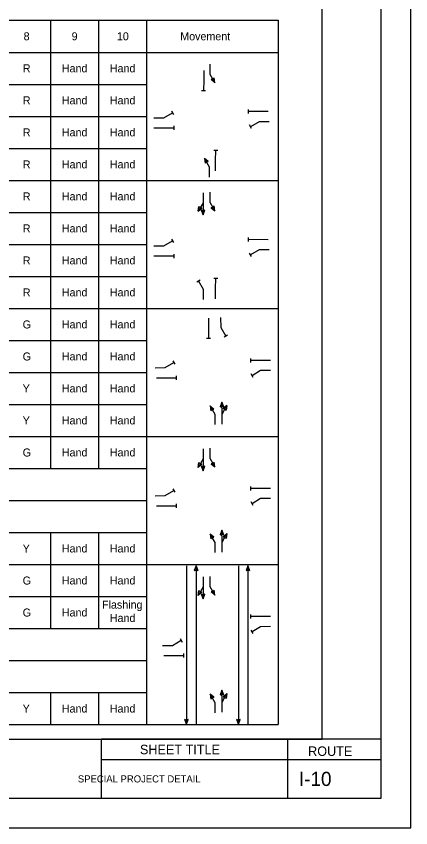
# Model space of a CAD drawing. Extents: x 515543 to 517243, y 660510 to 662861.
# Drawn here: x 516909 to 517243, y 660510 to 661197 of the extents above; entities that cross this region are included whole.
import ezdxf

# ---------------------------------------------------------------- set-up
doc = ezdxf.new("R2010")
doc.units = 0
for name, color, linetype in [('ANNO-SHT', 7, 'Continuous'), ('ANNO-TXT', 7, 'Continuous'), ('Default', 7, 'Continuous'), ('Level 6', 7, 'Continuous'), ('Level 62', 7, 'Continuous'), ('SHT-BDR', 7, 'Continuous'), ('SHT-BNDRY', 7, 'Continuous')]:
    doc.layers.add(name, color=color, linetype=linetype)

msp = doc.modelspace()

# ---------------------------------------------------------------- linework, layer by layer
at = {"layer": 'ANNO-TXT'}
for p, q in [((516980.81, 660567.94), (517138.45, 660567.94)), ((517138.45, 660567.94), (517217.52, 660567.94))]:
    msp.add_line(p, q, dxfattribs=at)
at = {"layer": 'Default'}
for p, q in [((516439.72, 661193.38), (517130.34, 661193.38)), ((516937.41, 661193.38), (516937.41, 660814.21)), ((516978.03, 661193.38), (516978.03, 660814.21)), ((517018.66, 661193.38), (517018.66, 660597.54)), ((517130.34, 661193.38), (517130.34, 660597.54)), ((516439.72, 661166.29), (517130.34, 661166.29)), ((517072.48, 661156.28), (517072.48, 661147.81)), ((517067.35, 661150.92), (517067.19, 661142.35)), ((517072.48, 661147.81), (517076.71, 661140.48)), ((516520.97, 661139.21), (517018.66, 661139.21)), ((517067.19, 661142.35), (517067.13, 661133.89)), ((517073.47, 661143.2), (517074.93, 661143.56)), ((517076.71, 661140.48), (517073.47, 661143.2)), ((517074.93, 661143.56), (517075.97, 661144.65)), ((517076.71, 661140.48), (517075.97, 661144.65)), ((517065.43, 661133.9), (517068.82, 661133.87)), ((517104.78, 661117.95), (517104.75, 661114.57)), ((516520.97, 661112.13), (517018.66, 661112.13)), ((516693.66, 661112.13), (517018.66, 661112.13)), ((517025.09, 661110.97), (517033.56, 661110.97)), ((517033.56, 661110.97), (517040.89, 661115.2)), ((517040.04, 661116.67), (517041.73, 661113.73)), ((517121.8, 661116.12), (517104.76, 661116.26)), ((517042.17, 661100.63), (517042.2, 661104.01)), ((517107.78, 661101.91), (517106.08, 661104.84)), ((517114.26, 661107.61), (517106.93, 661103.38)), ((517122.72, 661107.61), (517114.26, 661107.61)), ((517025.14, 661102.46), (517042.18, 661102.32)), ((516520.97, 661085.04), (517018.66, 661085.04)), ((517072.02, 661069.27), (517067.78, 661076.6)), ((517067.78, 661076.6), (517071.03, 661073.88)), ((517067.78, 661076.6), (517068.52, 661072.43)), ((517079.06, 661083.18), (517075.68, 661083.21)), ((517077.3, 661074.73), (517077.37, 661083.19)), ((517069.56, 661073.52), (517068.52, 661072.43)), ((517071.03, 661073.88), (517069.56, 661073.52)), ((517077.14, 661066.16), (517077.3, 661074.73)), ((517072.02, 661060.8), (517072.02, 661069.27)), ((516439.72, 661057.96), (517130.34, 661057.96)), ((516937.41, 661057.96), (516978.03, 661057.96)), ((516978.03, 661057.96), (517018.66, 661057.96)), ((517066.65, 661047.57), (517066.65, 661039.11)), ((517066.65, 661047.57), (517066.65, 661039.11)), ((517072.48, 661047.94), (517072.48, 661039.48)), ((517066.65, 661039.11), (517062.41, 661031.78)), ((517062.41, 661031.78), (517063.15, 661035.95)), ((517064.19, 661034.86), (517063.15, 661035.95)), ((517066.65, 661039.11), (517066.75, 661028.9)), ((517072.48, 661039.48), (517076.71, 661032.15)), ((517073.47, 661034.87), (517074.93, 661035.23)), ((517074.93, 661035.23), (517075.97, 661036.32)), ((517076.71, 661032.15), (517075.97, 661036.32)), ((516520.97, 661030.88), (517018.66, 661030.88)), ((517062.41, 661031.78), (517065.66, 661034.5)), ((517065.66, 661034.5), (517064.19, 661034.86)), ((517066.75, 661028.9), (517065.25, 661032.86)), ((517065.25, 661032.86), (517066.71, 661032.45)), ((517066.71, 661032.45), (517068.15, 661032.89)), ((517066.75, 661028.9), (517068.15, 661032.89)), ((517076.71, 661032.15), (517073.47, 661034.87)), ((517040.04, 661008.33), (517041.73, 661005.4)), ((517104.78, 661009.62), (517104.75, 661006.23)), ((517121.8, 661007.79), (517104.76, 661007.92)), ((516520.97, 661003.79), (517018.66, 661003.79)), ((516693.66, 661003.79), (517018.66, 661003.79)), ((517025.09, 661002.63), (517033.56, 661002.63)), ((517033.56, 661002.63), (517040.89, 661006.87)), ((517025.14, 660994.12), (517042.18, 660993.99)), ((517042.17, 660992.29), (517042.2, 660995.68)), ((517107.78, 660993.58), (517106.08, 660996.51)), ((517114.26, 660999.28), (517106.93, 660995.04)), ((517122.72, 660999.28), (517114.26, 660999.28)), ((516520.97, 660976.71), (517018.66, 660976.71)), ((517061.3, 660972.26), (517064.24, 660973.95)), ((517079.06, 660974.85), (517075.68, 660974.88)), ((517077.3, 660966.4), (517077.37, 660974.86)), ((517067, 660965.77), (517062.77, 660973.1)), ((517067, 660957.31), (517067, 660965.77)), ((517077.14, 660957.82), (517077.3, 660966.4)), ((516439.72, 660949.63), (517130.34, 660949.63)), ((517071.38, 660941.4), (517071.31, 660932.83)), ((517081.51, 660942.02), (517081.6, 660933.56)), ((517071.31, 660932.83), (517071.33, 660924.36)), ((517081.6, 660933.56), (517085.91, 660926.28)), ((517087.37, 660927.14), (517084.45, 660925.41)), ((516520.97, 660922.54), (517008.47, 660922.54)), ((516520.97, 660922.54), (517018.66, 660922.54)), ((517069.64, 660924.36), (517073.02, 660924.37)), ((517041.12, 660905.33), (517042.84, 660902.41)), ((517106.71, 660907.3), (517106.72, 660903.92)), ((517123.75, 660905.65), (517106.71, 660905.61)), ((517026.23, 660899.47), (517034.69, 660899.56)), ((517034.69, 660899.56), (517041.98, 660903.87)), ((516520.97, 660895.46), (517018.66, 660895.46)), ((516520.97, 660895.46), (517018.66, 660895.46)), ((516693.66, 660895.46), (517018.66, 660895.46)), ((516693.66, 660895.46), (517018.66, 660895.46)), ((517027.24, 660890.97), (517044.28, 660891.01)), ((517044.29, 660889.32), (517044.28, 660892.71)), ((517109, 660891.29), (517107.28, 660894.2)), ((517115.43, 660897.05), (517108.14, 660892.74)), ((517123.89, 660897.14), (517115.43, 660897.05)), ((517082.51, 660870.44), (517081.16, 660866.43)), ((517082.72, 660860.23), (517082.51, 660870.44)), ((517082.51, 660870.44), (517084.05, 660866.5)), ((516520.97, 660868.38), (517008.47, 660868.38)), ((516520.97, 660868.38), (517018.66, 660868.38)), ((517076.9, 660859.8), (517072.59, 660867.09)), ((517072.59, 660867.09), (517075.86, 660864.4)), ((517072.59, 660867.09), (517073.37, 660862.93)), ((517074.4, 660864.03), (517073.37, 660862.93)), ((517075.86, 660864.4), (517074.4, 660864.03)), ((517082.59, 660866.89), (517081.16, 660866.43)), ((517084.05, 660866.5), (517082.59, 660866.89)), ((517082.72, 660860.23), (517086.88, 660867.61)), ((517086.88, 660867.61), (517083.67, 660864.85)), ((517083.67, 660864.85), (517085.14, 660864.51)), ((517085.14, 660864.51), (517086.19, 660863.43)), ((517086.88, 660867.61), (517086.19, 660863.43)), ((517076.99, 660851.34), (517076.9, 660859.8)), ((517082.81, 660851.77), (517082.72, 660860.23)), ((517082.81, 660851.77), (517082.72, 660860.23)), ((516439.72, 660841.29), (517130.34, 660841.29)), ((517066.65, 660830.9), (517066.65, 660822.44)), ((517066.65, 660830.9), (517066.65, 660822.44)), ((517072.48, 660831.28), (517072.48, 660822.81)), ((517066.65, 660822.44), (517062.41, 660815.11)), ((517066.65, 660822.44), (517066.75, 660812.23)), ((517072.48, 660822.81), (517076.71, 660815.48)), ((517062.41, 660815.11), (517063.15, 660819.28)), ((517062.41, 660815.11), (517065.66, 660817.83)), ((517064.19, 660818.19), (517063.15, 660819.28)), ((517065.66, 660817.83), (517064.19, 660818.19)), ((517066.75, 660812.23), (517065.25, 660816.19)), ((517065.25, 660816.19), (517066.71, 660815.79)), ((517066.71, 660815.79), (517068.15, 660816.23)), ((517066.75, 660812.23), (517068.15, 660816.23)), ((517073.47, 660818.2), (517074.93, 660818.56)), ((517076.71, 660815.48), (517073.47, 660818.2)), ((517074.93, 660818.56), (517075.97, 660819.65)), ((517076.71, 660815.48), (517075.97, 660819.65)), ((516520.97, 660814.21), (517008.47, 660814.21)), ((516520.97, 660814.21), (517018.66, 660814.21)), ((517034.69, 660791.23), (517041.98, 660795.54)), ((517041.12, 660797), (517042.84, 660794.08)), ((517106.71, 660798.97), (517106.72, 660795.58)), ((517123.75, 660797.32), (517106.71, 660797.28)), ((517026.23, 660791.14), (517034.69, 660791.23)), ((517115.43, 660788.72), (517108.14, 660784.41)), ((517123.89, 660788.81), (517115.43, 660788.72)), ((516520.97, 660787.13), (517018.66, 660787.13)), ((516520.97, 660787.13), (517018.66, 660787.13)), ((516693.66, 660787.13), (517018.66, 660787.13)), ((516693.66, 660787.13), (517018.66, 660787.13)), ((517027.24, 660782.64), (517044.28, 660782.68)), ((517044.29, 660780.99), (517044.28, 660784.37)), ((517109, 660782.95), (517107.28, 660785.87)), ((517082.51, 660762.1), (517081.16, 660758.1)), ((517082.72, 660751.9), (517082.51, 660762.1)), ((517082.51, 660762.1), (517084.05, 660758.16)), ((516520.97, 660760.04), (517008.47, 660760.04)), ((516520.97, 660760.04), (517018.66, 660760.04)), ((516937.41, 660760.04), (516937.41, 660678.79)), ((516978.03, 660760.04), (516978.03, 660678.79)), ((517076.9, 660751.47), (517072.59, 660758.75)), ((517072.59, 660758.75), (517075.86, 660756.07)), ((517072.59, 660758.75), (517073.37, 660754.59)), ((517074.4, 660755.69), (517073.37, 660754.59)), ((517075.86, 660756.07), (517074.4, 660755.69)), ((517082.59, 660758.55), (517081.16, 660758.1)), ((517084.05, 660758.16), (517082.59, 660758.55)), ((517082.72, 660751.9), (517086.88, 660759.27)), ((517086.88, 660759.27), (517083.67, 660756.52)), ((517083.67, 660756.52), (517085.14, 660756.18)), ((517085.14, 660756.18), (517086.19, 660755.1)), ((517086.88, 660759.27), (517086.19, 660755.1)), ((517076.99, 660743), (517076.9, 660751.47)), ((517082.81, 660743.44), (517082.72, 660751.9)), ((517082.81, 660743.44), (517082.72, 660751.9)), ((516439.72, 660732.96), (517130.34, 660732.96)), ((517052.71, 660731.84), (517052.71, 660597.79)), ((517060.7, 660731.84), (517059.25, 660727.86)), ((517060.7, 660728.28), (517059.25, 660727.86)), ((517060.7, 660731.84), (517060.7, 660597.79)), ((517060.7, 660731.84), (517062.14, 660727.86)), ((517062.14, 660727.86), (517060.7, 660728.28)), ((517096.65, 660731.84), (517096.65, 660597.79)), ((517104.64, 660731.84), (517103.19, 660727.86)), ((517104.64, 660728.28), (517103.19, 660727.86)), ((517104.64, 660731.84), (517104.64, 660597.79)), ((517104.64, 660731.84), (517106.09, 660727.86)), ((517106.09, 660727.86), (517104.64, 660728.28)), ((517066.65, 660722.57), (517066.65, 660714.11)), ((517066.65, 660722.57), (517066.65, 660714.11)), ((517072.48, 660722.94), (517072.48, 660714.48)), ((517066.65, 660714.11), (517062.41, 660706.78)), ((517066.65, 660714.11), (517066.75, 660703.9)), ((517072.48, 660714.48), (517076.71, 660707.15)), ((516520.97, 660705.88), (517008.47, 660705.88)), ((516520.97, 660705.88), (517018.66, 660705.88)), ((517062.41, 660706.78), (517063.15, 660710.95)), ((517062.41, 660706.78), (517065.66, 660709.5)), ((517064.19, 660709.86), (517063.15, 660710.95)), ((517065.66, 660709.5), (517064.19, 660709.86)), ((517066.75, 660703.9), (517065.25, 660707.86)), ((517065.25, 660707.86), (517066.71, 660707.45)), ((517066.71, 660707.45), (517068.15, 660707.89)), ((517066.75, 660703.9), (517068.15, 660707.89)), ((517073.47, 660709.87), (517074.93, 660710.23)), ((517076.71, 660707.15), (517073.47, 660709.87)), ((517074.93, 660710.23), (517075.97, 660711.32)), ((517076.71, 660707.15), (517075.97, 660711.32)), ((517106.71, 660690.63), (517106.72, 660687.25)), ((517123.75, 660688.98), (517106.71, 660688.94)), ((516520.97, 660678.79), (517018.66, 660678.79)), ((516520.97, 660678.79), (517018.66, 660678.79)), ((516693.66, 660678.79), (517018.66, 660678.79)), ((516693.66, 660678.79), (517018.66, 660678.79)), ((517115.43, 660680.38), (517108.14, 660676.08)), ((517123.89, 660680.47), (517115.43, 660680.38)), ((517109, 660674.62), (517107.28, 660677.53)), ((517032.45, 660664.46), (517040.91, 660664.54)), ((517040.91, 660664.54), (517048.2, 660668.85)), ((517047.33, 660670.31), (517049.06, 660667.4)), ((517050.5, 660654.3), (517050.5, 660657.69)), ((516520.97, 660651.71), (517008.47, 660651.71)), ((516520.97, 660651.71), (517018.66, 660651.71)), ((517033.46, 660655.95), (517050.5, 660656)), ((516520.97, 660624.63), (517018.66, 660624.63)), ((516520.97, 660624.63), (517008.47, 660624.63)), ((516520.97, 660624.63), (517008.47, 660624.63)), ((516937.41, 660624.63), (516937.41, 660597.54)), ((516978.03, 660624.63), (516978.03, 660597.54)), ((517076.9, 660616.05), (517072.59, 660623.34)), ((517072.59, 660623.34), (517075.86, 660620.65)), ((517072.59, 660623.34), (517073.37, 660619.18)), ((517082.51, 660626.69), (517081.16, 660622.68)), ((517082.72, 660616.48), (517082.51, 660626.69)), ((517082.51, 660626.69), (517084.05, 660622.75)), ((517082.72, 660616.48), (517086.88, 660623.86)), ((517086.88, 660623.86), (517083.67, 660621.1)), ((517086.88, 660623.86), (517086.19, 660619.68)), ((517074.4, 660620.28), (517073.37, 660619.18)), ((517075.86, 660620.65), (517074.4, 660620.28)), ((517082.59, 660623.14), (517081.16, 660622.68)), ((517084.05, 660622.75), (517082.59, 660623.14)), ((517082.81, 660608.02), (517082.72, 660616.48)), ((517082.81, 660608.02), (517082.72, 660616.48)), ((517083.67, 660621.1), (517085.14, 660620.76)), ((517085.14, 660620.76), (517086.19, 660619.68)), ((517076.99, 660607.59), (517076.9, 660616.05)), ((516439.72, 660597.54), (517130.34, 660597.54)), ((517052.71, 660597.79), (517051.26, 660601.76)), ((517051.26, 660601.76), (517052.71, 660601.34)), ((517052.71, 660597.79), (517054.15, 660601.76)), ((517052.71, 660601.34), (517054.15, 660601.76)), ((517096.65, 660597.79), (517095.2, 660601.76)), ((517095.2, 660601.76), (517096.65, 660601.34)), ((517096.65, 660597.79), (517098.1, 660601.76)), ((517096.65, 660601.34), (517098.1, 660601.76))]:
    msp.add_line(p, q, dxfattribs=at)
for points in [[(517073.47, 661143.2), (517076.71, 661140.48), (517075.97, 661144.65), (517074.93, 661143.56), (517073.47, 661143.2)], [(517071.03, 661073.88), (517067.78, 661076.6), (517068.52, 661072.43), (517069.56, 661073.52), (517071.03, 661073.88)], [(517065.66, 661034.5), (517062.41, 661031.78), (517063.15, 661035.95), (517064.19, 661034.86), (517065.66, 661034.5)], [(517073.47, 661034.87), (517076.71, 661032.15), (517075.97, 661036.32), (517074.93, 661035.23), (517073.47, 661034.87)], [(517065.25, 661032.86), (517066.75, 661028.9), (517068.15, 661032.89), (517066.71, 661032.45), (517065.25, 661032.86)], [(517084.05, 660866.5), (517082.51, 660870.44), (517081.16, 660866.43), (517082.59, 660866.89), (517084.05, 660866.5)], [(517075.86, 660864.4), (517072.59, 660867.09), (517073.37, 660862.93), (517074.4, 660864.03), (517075.86, 660864.4)], [(517083.67, 660864.85), (517086.88, 660867.61), (517086.19, 660863.43), (517085.14, 660864.51), (517083.67, 660864.85)], [(517065.66, 660817.83), (517062.41, 660815.11), (517063.15, 660819.28), (517064.19, 660818.19), (517065.66, 660817.83)], [(517065.25, 660816.19), (517066.75, 660812.23), (517068.15, 660816.23), (517066.71, 660815.79), (517065.25, 660816.19)], [(517073.47, 660818.2), (517076.71, 660815.48), (517075.97, 660819.65), (517074.93, 660818.56), (517073.47, 660818.2)], [(517084.05, 660758.16), (517082.51, 660762.1), (517081.16, 660758.1), (517082.59, 660758.55), (517084.05, 660758.16)], [(517075.86, 660756.07), (517072.59, 660758.75), (517073.37, 660754.59), (517074.4, 660755.69), (517075.86, 660756.07)], [(517083.67, 660756.52), (517086.88, 660759.27), (517086.19, 660755.1), (517085.14, 660756.18), (517083.67, 660756.52)], [(517062.14, 660727.86), (517060.7, 660731.84), (517059.25, 660727.86), (517060.7, 660728.28), (517062.14, 660727.86)], [(517106.09, 660727.86), (517104.64, 660731.84), (517103.19, 660727.86), (517104.64, 660728.28), (517106.09, 660727.86)], [(517065.66, 660709.5), (517062.41, 660706.78), (517063.15, 660710.95), (517064.19, 660709.86), (517065.66, 660709.5)], [(517065.25, 660707.86), (517066.75, 660703.9), (517068.15, 660707.89), (517066.71, 660707.45), (517065.25, 660707.86)], [(517073.47, 660709.87), (517076.71, 660707.15), (517075.97, 660711.32), (517074.93, 660710.23), (517073.47, 660709.87)], [(517075.86, 660620.65), (517072.59, 660623.34), (517073.37, 660619.18), (517074.4, 660620.28), (517075.86, 660620.65)], [(517084.05, 660622.75), (517082.51, 660626.69), (517081.16, 660622.68), (517082.59, 660623.14), (517084.05, 660622.75)], [(517083.67, 660621.1), (517086.88, 660623.86), (517086.19, 660619.68), (517085.14, 660620.76), (517083.67, 660621.1)], [(517051.26, 660601.76), (517052.71, 660597.79), (517054.15, 660601.76), (517052.71, 660601.34), (517051.26, 660601.76)], [(517095.2, 660601.76), (517096.65, 660597.79), (517098.1, 660601.76), (517096.65, 660601.34), (517095.2, 660601.76)]]:
    msp.add_lwpolyline(points, dxfattribs=at)
at = {"layer": 'Level 6'}
msp.add_line((517217.52, 660585.3), (516980.81, 660585.3), dxfattribs=at)
at = {"layer": 'Level 62'}
msp.add_lwpolyline([(515542.51, 660510.25), (517242.52, 660510.25), (517242.52, 661610.25), (515542.51, 661610.25)], close=True, dxfattribs=at)
at = {"layer": 'SHT-BDR'}
msp.add_lwpolyline([(515667.5, 660585.3), (517167.5, 660585.3), (517167.5, 661535.3), (515667.5, 661535.3)], close=True, dxfattribs=at)
at = {"layer": 'SHT-BNDRY'}
for p, q in [((516980.81, 660535.25), (516980.81, 660585.3)), ((517138.45, 660535.25), (517138.45, 660585.3))]:
    msp.add_line(p, q, dxfattribs=at)
msp.add_lwpolyline([(515605.01, 660535.25), (517217.52, 660535.25), (517217.52, 661585.25), (515605.01, 661585.25)], close=True, dxfattribs=at)

# ---------------------------------------------------------------- texts
at = {"layer": 'ANNO-SHT'}
for s, height, p in [('         SPECIAL PROJECT DETAIL         ', 6, (516940.64, 660548.59)), ('  I-10  ', 12, (517138.85, 660545.59))]:
    msp.add_text(s, height=height, dxfattribs=at).set_placement(p)
at = {"layer": 'ANNO-TXT'}
for s, p in [('SHEET TITLE', (517013.24, 660572.46)), ('ROUTE', (517155.61, 660571.05))]:
    msp.add_text(s, height=8, dxfattribs=at).set_placement(p)
at = {"layer": 'Default'}
for s, height, p in [('8', 6.77, (516914.78, 661176.49)), ('9', 6.77, (516955.43, 661176.49)), ('10', 6.771, (516993.74, 661176.49)), ('Movement', 6.771, (517047.36, 661176.5)), ('R', 6.77, (516914.11, 661149.37)), ('Hand', 6.771, (516947.14, 661149.42)), ('Hand', 6.771, (516987.76, 661149.42)), ('R', 6.77, (516914.11, 661122.28)), ('Hand', 6.771, (516947.14, 661122.34)), ('Hand', 6.771, (516987.76, 661122.34)), ('R', 6.77, (516914.11, 661095.2)), ('Hand', 6.771, (516947.14, 661095.25)), ('Hand', 6.771, (516987.76, 661095.25)), ('R', 6.77, (516914.11, 661068.12)), ('Hand', 6.771, (516947.14, 661068.17)), ('Hand', 6.771, (516987.76, 661068.17)), ('R', 6.77, (516914.11, 661041.03)), ('Hand', 6.771, (516947.14, 661041.09)), ('Hand', 6.771, (516987.76, 661041.09)), ('R', 6.77, (516914.11, 661013.95)), ('Hand', 6.771, (516947.14, 661014)), ('Hand', 6.771, (516987.76, 661014)), ('Hand', 6.771, (516947.14, 660986.92)), ('Hand', 6.771, (516987.76, 660986.92)), ('R', 6.77, (516914.11, 660986.87)), ('R', 6.77, (516914.11, 660959.78)), ('Hand', 6.771, (516947.14, 660959.84)), ('Hand', 6.771, (516987.76, 660959.84)), ('G', 6.77, (516913.96, 660932.7)), ('Hand', 6.771, (516947.14, 660932.75)), ('Hand', 6.771, (516947.14, 660932.75)), ('Hand', 6.771, (516987.76, 660932.75)), ('Hand', 6.771, (516987.76, 660932.75)), ('G', 6.77, (516913.96, 660905.61)), ('Hand', 6.771, (516947.14, 660905.67)), ('Hand', 6.771, (516947.14, 660905.67)), ('Hand', 6.771, (516987.76, 660905.67)), ('Hand', 6.771, (516987.76, 660905.67)), ('Y', 6.77, (516913.99, 660878.53)), ('Hand', 6.771, (516947.14, 660878.59)), ('Hand', 6.771, (516987.76, 660878.59)), ('Y', 6.77, (516913.99, 660851.45)), ('Hand', 6.771, (516947.14, 660851.5)), ('Hand', 6.771, (516987.76, 660851.5)), ('G', 6.77, (516913.96, 660824.36)), ('Hand', 6.771, (516947.14, 660824.42)), ('Hand', 6.771, (516947.14, 660824.42)), ('Hand', 6.771, (516987.76, 660824.42)), ('Hand', 6.771, (516987.76, 660824.42)), ('Y', 6.77, (516913.99, 660743.12)), ('Hand', 6.771, (516947.14, 660743.17)), ('Hand', 6.771, (516987.76, 660743.17)), ('G', 6.77, (516913.96, 660716.03)), ('Hand', 6.771, (516947.14, 660716.09)), ('Hand', 6.771, (516987.76, 660716.09)), ('Hand', 6.771, (516987.76, 660716.09)), ('Flashing', 6.771, (516981.17, 660695.65)), ('G', 6.77, (516913.96, 660688.95)), ('Hand', 6.771, (516947.14, 660689)), ('Hand', 6.771, (516987.76, 660684.37)), ('Y', 6.77, (516913.99, 660607.7)), ('Hand', 6.771, (516947.14, 660607.75)), ('Hand', 6.771, (516987.76, 660607.75))]:
    msp.add_text(s, height=height, dxfattribs=at).set_placement(p)

doc.saveas('drawing.dxf')
